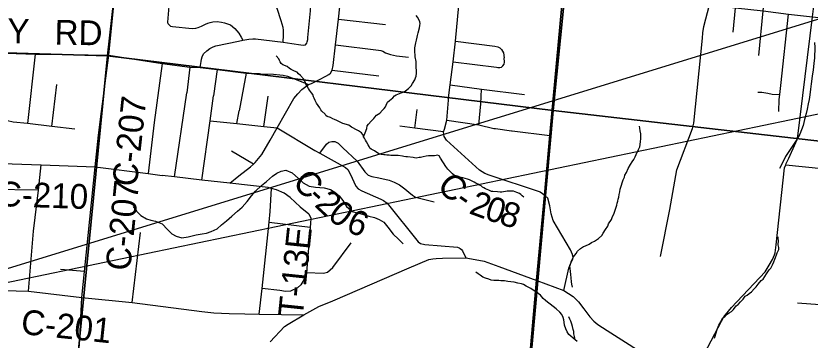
# Model space of a CAD drawing. Extents: x 0 to 34, y -2 to 22.
# Drawn here: x 5.919 to 7.738, y 16.052 to 16.795 of the extents above; entities that cross this region are included whole.
import ezdxf

# ---------------------------------------------------------------- set-up
doc = ezdxf.new("R2010")
doc.units = 0
for name, color, linetype in [('GM_X_City_Street', 7, 'Continuous'), ('GM_X_County_Road', 7, 'Continuous'), ('GM_X_County_Road_Text', 7, 'Continuous'), ('GM_X_Minor_River', 7, 'Continuous'), ('GM_X_Rail_Line', 7, 'Continuous'), ('GM_X_Section', 7, 'Continuous'), ('GM_X_Township_Road', 7, 'Continuous'), ('GM_X_Township_Road_Text', 7, 'Continuous'), ('SH_Data', 7, 'Continuous')]:
    doc.layers.add(name, color=color, linetype=linetype)

msp = doc.modelspace()

# ---------------------------------------------------------------- linework, layer by layer
at = {"layer": 'GM_X_City_Street'}
for p, q in [((6.6581, 16.7874), (6.7659, 16.7749)), ((6.6435, 16.6702), (6.7501, 16.6574)), ((6.984, 16.5934), (6.9858, 16.6272)), ((6.2824, 16.4258), (6.3103, 16.6188)), ((6.4872, 16.5414), (6.497, 16.6107)), ((6.4248, 16.548), (6.4308, 16.5773)), ((6.4631, 16.4553), (6.4127, 16.4848)), ((6.5018, 16.3463), (6.5046, 16.3991)), ((7.7088, 16.1375), (7.7832, 16.1312))]:
    msp.add_line(p, q, dxfattribs=at)
for points in [[(7.6208, 16.7039), (7.6305, 16.8061), (7.6519, 17.0096), (7.6625, 17.1149), (7.6673, 17.1631), (7.6723, 17.2097), (7.6784, 17.2661), (7.6863, 17.3438)], [(7.3952, 16.2431), (7.4169, 16.3509), (7.4324, 16.4422), (7.4685, 16.5369), (7.4715, 16.5488), (7.4913, 16.7438), (7.4923, 16.7556), (7.4943, 16.7707), (7.5074, 16.8201), (7.5148, 16.8521), (7.5294, 16.9123), (7.5314, 16.9213), (7.5357, 16.9362), (7.5392, 16.9489), (7.5442, 16.9615), (7.5505, 16.9743), (7.5547, 16.9827), (7.5547, 16.9956), (7.5546, 17.0201), (7.5573, 17.126)], [(6.5854, 16.7319), (6.5865, 16.7357), (6.5874, 16.7403), (6.5877, 16.7449), (6.5941, 16.8067), (6.5949, 16.8186), (6.5946, 16.8234), (6.5938, 16.8272), (6.5917, 16.8341), (6.5826, 16.851), (6.5807, 16.8593), (6.5804, 16.8706), (6.5892, 16.9384)], [(6.4094, 16.4112), (6.4299, 16.4281), (6.4567, 16.4492), (6.4631, 16.4553), (6.4669, 16.4591), (6.4823, 16.4772), (6.5016, 16.5099), (6.5176, 16.5383), (6.5556, 16.6057), (6.5651, 16.6164), (6.5739, 16.6258), (6.5891, 16.6379), (6.5959, 16.6397), (6.6145, 16.6491), (6.6292, 16.6569), (6.6356, 16.6607), (6.6394, 16.6638), (6.6435, 16.6702), (6.6458, 16.681), (6.6513, 16.7287), (6.6581, 16.7874), (6.6735, 16.9296)], [(6.5309, 16.7348), (6.5322, 16.7509), (6.532, 16.7619), (6.5314, 16.7683), (6.5269, 16.7835), (6.5176, 16.8118), (6.5134, 16.8189), (6.5074, 16.8272), (6.4893, 16.8506), (6.4799, 16.8633), (6.465, 16.8844), (6.4428, 16.9198)], [(7.5615, 16.7575), (7.5671, 16.8129), (7.5712, 16.8506), (7.5754, 16.9165)], [(6.2678, 16.7768), (6.267, 16.7801), (6.2702, 16.8171), (6.2713, 16.8208), (6.2724, 16.8225), (6.274, 16.8244), (6.2763, 16.8259), (6.2787, 16.8266), (6.3175, 16.8231), (6.3379, 16.8205), (6.3438, 16.8209), (6.3493, 16.822), (6.3608, 16.827), (6.3671, 16.8295), (6.3726, 16.8306), (6.3799, 16.831), (6.4356, 16.8227)], [(7.6664, 16.5759), (7.6671, 16.6032), (7.669, 16.6144), (7.6709, 16.6349), (7.6888, 16.7991)], [(6.2678, 16.7768), (6.27, 16.774), (6.2734, 16.7715), (6.2776, 16.7705), (6.3225, 16.7657), (6.3312, 16.7669), (6.3368, 16.7683), (6.3444, 16.7714), (6.3531, 16.7761), (6.3587, 16.7782), (6.3641, 16.7798), (6.3703, 16.7812), (6.3801, 16.7817), (6.3897, 16.7807), (6.3972, 16.7792), (6.4103, 16.7741), (6.4202, 16.7661), (6.4293, 16.7552), (6.4348, 16.7458), (6.4391, 16.7393)], [(6.3415, 16.6766), (6.3431, 16.6901), (6.3442, 16.6957), (6.346, 16.7011), (6.3487, 16.7076), (6.3561, 16.7149), (6.3636, 16.7204), (6.3712, 16.7242), (6.3771, 16.7264), (6.4286, 16.7365), (6.4391, 16.7393), (6.4523, 16.7412), (6.4619, 16.7424), (6.4675, 16.7424), (6.4866, 16.7399), (6.5309, 16.7348), (6.5513, 16.7318), (6.572, 16.7287), (6.5782, 16.7278), (6.5824, 16.7288), (6.5854, 16.7319)], [(6.9257, 16.7372), (7.016, 16.7256), (7.0227, 16.7238), (7.0275, 16.7215), (7.0312, 16.718), (7.0339, 16.714), (7.0356, 16.7098), (7.0372, 16.6984)], [(6.6513, 16.7287), (6.7494, 16.7165), (6.755, 16.7156), (6.7597, 16.714), (6.7658, 16.7101), (6.7767, 16.7061), (6.7911, 16.7029), (6.8185, 16.7001)], [(6.9205, 16.6895), (7.0201, 16.6771), (7.023, 16.6767), (7.0272, 16.6767), (7.0313, 16.6776), (7.0345, 16.6801), (7.037, 16.6841), (7.0378, 16.6885), (7.0372, 16.6984)], [(6.9137, 16.6365), (6.9858, 16.6272), (7.0838, 16.6148)], [(6.3452, 16.4186), (6.3637, 16.5544), (6.3715, 16.6115)], [(7.6182, 16.6199), (7.6272, 16.6202), (7.6412, 16.6174), (7.6509, 16.6152), (7.669, 16.6144)], [(6.3637, 16.5544), (6.4248, 16.548), (6.4872, 16.5414), (6.5176, 16.5383), (6.604, 16.4859)], [(7.6823, 16.4535), (7.7649, 16.4449), (7.8088, 16.4403), (7.8136, 16.4399), (7.8494, 16.4361), (7.854, 16.4356), (7.859, 16.4351)], [(6.5699, 16.3571), (6.5474, 16.3789), (6.5333, 16.3885), (6.5161, 16.3963), (6.5046, 16.3991), (6.4965, 16.4011), (6.4094, 16.4112), (6.3452, 16.4186), (6.2824, 16.4258), (6.2538, 16.4291)]]:
    msp.add_lwpolyline(points, dxfattribs=at)
at = {"layer": 'GM_X_County_Road'}
msp.add_line((6.4461, 16.6638), (6.4308, 16.5773), dxfattribs=at)
for points in [[(6.9101, 16.6067), (6.9137, 16.6365), (6.9205, 16.6895), (6.9257, 16.7372), (6.9402, 16.8926), (6.9541, 16.9885), (6.9627, 17.0648), (6.9675, 17.1013), (6.9705, 17.1364), (6.9735, 17.164), (6.9816, 17.2685), (6.9956, 17.3996)], [(6.1316, 16.7045), (6.1476, 16.867), (6.1481, 16.8719), (6.1555, 16.9383), (6.1634, 17.0422)], [(7.4637, 15.9561), (7.4964, 16.0209), (7.5352, 16.0954), (7.5404, 16.1047), (7.558, 16.1266), (7.6348, 16.2084), (7.6443, 16.2237), (7.6522, 16.2368), (7.6565, 16.247), (7.6579, 16.2514), (7.6603, 16.2699), (7.6794, 16.4469), (7.6823, 16.4535), (7.6835, 16.4563), (7.6891, 16.469), (7.7056, 16.5046), (7.7084, 16.5106), (7.7098, 16.5193), (7.7437, 16.7928), (7.7563, 16.8973), (7.7576, 16.9073)], [(7.4025, 16.8396), (7.4054, 16.8392), (7.4318, 16.8345), (7.4767, 16.8251), (7.5074, 16.8201), (7.5322, 16.8169), (7.5671, 16.8129), (7.6305, 16.8061), (7.6888, 16.7991), (7.6957, 16.7979), (7.7437, 16.7928), (7.806, 16.7861), (7.8851, 16.7752)], [(5.7642, 16.7123), (5.9195, 16.7087), (5.9635, 16.7073), (5.991, 16.7068), (6.1316, 16.7045)], [(6.0335, 15.759), (6.0434, 15.8458), (6.0484, 15.8945), (6.0497, 15.9221), (6.0535, 15.9613), (6.0646, 16.041), (6.0702, 16.1495), (6.0762, 16.2088), (6.1008, 16.4492), (6.1082, 16.5217), (6.1149, 16.5754), (6.1316, 16.7045)], [(6.1316, 16.7045), (6.254, 16.6855), (6.3172, 16.6773), (6.3415, 16.6766), (6.3799, 16.6719), (6.4461, 16.6638), (6.4767, 16.6624), (6.48, 16.6623)], [(6.48, 16.6623), (6.5088, 16.6611), (6.5236, 16.66), (6.531, 16.6591), (6.5408, 16.6566), (6.5573, 16.6505), (6.5891, 16.6379)], [(6.9004, 16.5355), (6.9063, 16.5557), (6.9095, 16.6017), (6.9101, 16.6067)], [(7.1196, 16.3908), (7.118, 16.3919), (7.0031, 16.4295), (6.9934, 16.4335), (6.9811, 16.4414), (6.9049, 16.5098), (6.8998, 16.5183), (6.8994, 16.5226), (6.8984, 16.5288), (6.9004, 16.5355)], [(6.604, 16.4859), (6.6148, 16.4799), (6.6741, 16.4472), (6.679, 16.4426), (6.6844, 16.4326), (6.698, 16.4045), (6.7031, 16.3987), (6.711, 16.3939), (6.7548, 16.3749), (6.7611, 16.3714), (6.7693, 16.3655), (6.8407, 16.2771), (6.846, 16.2735), (6.8557, 16.2706), (6.9302, 16.2645), (6.9343, 16.2632), (6.9369, 16.2617), (6.9399, 16.2591), (6.9417, 16.2562), (6.9492, 16.2405)], [(5.7771, 16.4603), (5.9772, 16.4534), (6.1008, 16.4492), (6.222, 16.4333), (6.2538, 16.4291)], [(7.1743, 16.1656), (7.1852, 16.2164), (7.1893, 16.2266), (7.1945, 16.2371), (7.195, 16.2412), (7.194, 16.2477), (7.1894, 16.2584), (7.1495, 16.3262), (7.1446, 16.3408), (7.1417, 16.3598), (7.1376, 16.377), (7.1302, 16.3835), (7.1196, 16.3908)], [(6.5014, 16.0479), (6.5342, 16.083), (6.5426, 16.0881), (6.5789, 16.1097), (6.613, 16.1287), (6.6448, 16.1416), (6.8198, 16.2173), (6.865, 16.2363), (6.8742, 16.2379), (6.8817, 16.2385), (6.8962, 16.2396), (6.9492, 16.2405), (6.971, 16.2361), (6.9918, 16.2325), (7.0255, 16.2203), (7.112, 16.1885)], [(5.7506, 16.1784), (5.8081, 16.1722), (5.8625, 16.1664), (5.9478, 16.1635), (6.0702, 16.1495), (6.1855, 16.1382), (6.345, 16.1172), (6.3726, 16.1142), (6.4077, 16.1125), (6.4437, 16.112), (6.4766, 16.1114), (6.5789, 16.1097)], [(7.112, 16.1885), (7.1743, 16.1656), (7.1952, 16.1517), (7.2074, 16.1396), (7.2198, 16.1237), (7.2337, 16.1048), (7.2425, 16.0951), (7.2522, 16.0876), (7.2734, 16.0738), (7.3847, 16.003), (7.4637, 15.9561)]]:
    msp.add_lwpolyline(points, dxfattribs=at)
at = {"layer": 'GM_X_Minor_River'}
for points in [[(6.7155, 16.5176), (6.7188, 16.5267), (6.7229, 16.5369), (6.7238, 16.5426), (6.727, 16.5463), (6.7325, 16.5537), (6.7391, 16.5593), (6.7411, 16.5623), (6.7446, 16.5675), (6.7524, 16.5722), (6.759, 16.5785), (6.7625, 16.5822), (6.7657, 16.5867), (6.7673, 16.5905), (6.7702, 16.5969), (6.7748, 16.6009), (6.7822, 16.6072), (6.7865, 16.6113), (6.79, 16.6135), (6.7939, 16.6153), (6.7973, 16.6167), (6.8015, 16.6181), (6.8073, 16.6206), (6.8104, 16.622), (6.8154, 16.6261), (6.8186, 16.6287), (6.8244, 16.6346), (6.8272, 16.6398), (6.8328, 16.6481), (6.8344, 16.653), (6.8357, 16.6567), (6.8362, 16.6632), (6.8364, 16.6697), (6.8358, 16.6762), (6.8356, 16.6823), (6.8357, 16.6857), (6.8355, 16.6906), (6.8338, 16.7006), (6.8332, 16.7059), (6.8326, 16.7117), (6.8329, 16.7216), (6.8351, 16.7329), (6.8368, 16.7394), (6.8381, 16.7458), (6.839, 16.7496), (6.8403, 16.7556), (6.8436, 16.7674), (6.8445, 16.773), (6.8447, 16.7776), (6.8444, 16.7814), (6.8419, 16.7868), (6.8389, 16.7915), (6.836, 16.7954)], [(7.748, 16.7339), (7.7489, 16.7225), (7.7484, 16.6989), (7.7466, 16.6853), (7.7448, 16.6713), (7.7429, 16.6565), (7.7406, 16.6391), (7.7388, 16.6266), (7.7374, 16.6141), (7.7357, 16.6035), (7.7335, 16.5936), (7.7314, 16.5808), (7.7293, 16.5709), (7.7255, 16.5573), (7.7218, 16.5437), (7.7145, 16.5234), (7.7063, 16.5095), (7.6996, 16.4998), (7.691, 16.4863), (7.6816, 16.4728), (7.6744, 16.4581), (7.6681, 16.4453)], [(6.5914, 16.6243), (6.5896, 16.6282), (6.5852, 16.6352), (6.5831, 16.6394), (6.5813, 16.6437), (6.5781, 16.6506), (6.5706, 16.658), (6.5666, 16.6616), (6.5629, 16.6655), (6.5568, 16.6679), (6.5493, 16.6716), (6.5456, 16.6744), (6.54, 16.6787), (6.5302, 16.6824), (6.5269, 16.6859), (6.5243, 16.6894), (6.5229, 16.6929), (6.5215, 16.6967), (6.5152, 16.703)], [(7.0826, 16.3794), (7.0788, 16.3826), (7.0755, 16.3854), (7.0721, 16.3874), (7.0661, 16.3902), (7.0624, 16.3918), (7.059, 16.3927), (7.0556, 16.3931), (7.0498, 16.3929), (7.0445, 16.3927), (7.0323, 16.3908), (7.0281, 16.3909), (7.0221, 16.3918), (7.0114, 16.3921), (7.0084, 16.3926), (7.0054, 16.3938), (7.0024, 16.395), (6.9982, 16.3967), (6.9949, 16.3986), (6.9911, 16.4007), (6.9881, 16.4026), (6.9844, 16.4054), (6.9806, 16.4067), (6.9769, 16.4091), (6.9724, 16.4111), (6.9683, 16.4139), (6.9653, 16.4155), (6.9611, 16.4175), (6.9581, 16.4187), (6.9536, 16.4204), (6.9423, 16.4233), (6.9389, 16.4242), (6.9351, 16.4255), (6.9279, 16.4264), (6.9242, 16.4284), (6.919, 16.4328), (6.916, 16.4355), (6.9082, 16.4433), (6.9035, 16.4499), (6.8918, 16.4686), (6.8885, 16.4744), (6.8848, 16.4752), (6.8813, 16.4749), (6.8775, 16.4743), (6.8676, 16.4742), (6.8642, 16.4739), (6.8585, 16.4733), (6.8516, 16.4716), (6.8458, 16.4702), (6.8428, 16.4699), (6.8359, 16.469), (6.8321, 16.4695), (6.8291, 16.4699), (6.8158, 16.4718), (6.812, 16.4719), (6.8079, 16.4728), (6.8048, 16.4736), (6.7942, 16.4747), (6.787, 16.4749), (6.7775, 16.4748), (6.7741, 16.4753), (6.7688, 16.4758), (6.7646, 16.4763), (6.7616, 16.4764), (6.7559, 16.4769), (6.7517, 16.4782), (6.7457, 16.4818), (6.7405, 16.4853), (6.7326, 16.489), (6.7297, 16.4914), (6.7282, 16.4956), (6.7261, 16.4995), (6.7217, 16.5061), (6.7199, 16.5099), (6.7177, 16.5145), (6.7155, 16.5176), (6.7152, 16.5207), (6.7105, 16.5265), (6.7037, 16.5317), (6.7004, 16.5329), (6.688, 16.5394), (6.6817, 16.5445), (6.6677, 16.5483), (6.6632, 16.5507), (6.6542, 16.5548), (6.6485, 16.5572), (6.6448, 16.5592), (6.6399, 16.562), (6.632, 16.5642), (6.6286, 16.5665), (6.6272, 16.5696), (6.6198, 16.5767), (6.6176, 16.5798), (6.615, 16.5844), (6.6077, 16.5945), (6.6045, 16.6007), (6.602, 16.6065), (6.6005, 16.6096), (6.5988, 16.6146), (6.5962, 16.6181), (6.5914, 16.6243)], [(7.1937, 16.173), (7.1924, 16.1799), (7.1914, 16.1849), (7.1909, 16.1944), (7.19, 16.2024), (7.189, 16.2093), (7.1884, 16.2158), (7.1878, 16.2215), (7.1899, 16.2283), (7.1915, 16.2332), (7.194, 16.2381), (7.1964, 16.2426), (7.2023, 16.2504), (7.2055, 16.2553), (7.2121, 16.262), (7.2187, 16.266), (7.2237, 16.2681), (7.2318, 16.2717), (7.2372, 16.2757), (7.2441, 16.2782), (7.2488, 16.2819), (7.2534, 16.2844), (7.2612, 16.2915), (7.2644, 16.2971), (7.2692, 16.3053), (7.2747, 16.3128), (7.2764, 16.3181), (7.2831, 16.3278), (7.2856, 16.3353), (7.2888, 16.3406), (7.2908, 16.347), (7.2938, 16.3561), (7.295, 16.3606), (7.2963, 16.3655), (7.2976, 16.37), (7.2988, 16.375), (7.2997, 16.3795), (7.301, 16.3856), (7.3023, 16.3912), (7.3032, 16.3973), (7.3062, 16.4067), (7.3078, 16.412), (7.3095, 16.4188), (7.3127, 16.4248), (7.314, 16.4294), (7.3172, 16.4361), (7.3216, 16.4452), (7.3265, 16.4545), (7.3304, 16.4601), (7.334, 16.4654), (7.3376, 16.4718), (7.34, 16.477), (7.3449, 16.4883), (7.3477, 16.4943), (7.349, 16.5004), (7.3496, 16.5072), (7.3505, 16.5129), (7.3507, 16.5194), (7.3504, 16.5243), (7.3491, 16.5312), (7.3481, 16.5373), (7.3471, 16.5419)], [(6.1879, 16.3577), (6.1953, 16.3473), (6.2049, 16.3376), (6.2184, 16.3293), (6.2282, 16.3264), (6.2391, 16.3243), (6.2538, 16.3183), (6.266, 16.3051), (6.2764, 16.2954), (6.2865, 16.2898), (6.299, 16.2861), (6.3134, 16.2881), (6.3321, 16.293), (6.3454, 16.2954), (6.3553, 16.2971), (6.366, 16.3007), (6.3798, 16.3065), (6.3903, 16.3157), (6.4011, 16.325), (6.4138, 16.3357), (6.427, 16.3476), (6.4374, 16.3565), (6.4491, 16.3696), (6.4585, 16.3823), (6.4678, 16.3927), (6.4814, 16.4057), (6.493, 16.4154), (6.5069, 16.4276), (6.5169, 16.4346), (6.5265, 16.439), (6.5375, 16.4414), (6.5518, 16.4354), (6.5663, 16.4221), (6.5771, 16.4124), (6.5906, 16.4045), (6.6049, 16.4023), (6.6254, 16.4004), (6.6393, 16.397), (6.6494, 16.3907), (6.6591, 16.3825), (6.6676, 16.3717), (6.6764, 16.3582), (6.6898, 16.3466), (6.6996, 16.3433), (6.7128, 16.34), (6.7271, 16.3359), (6.7407, 16.3329), (6.7508, 16.3281), (6.7616, 16.3218), (6.7712, 16.3102), (6.783, 16.2948), (6.7953, 16.2827), (6.8057, 16.2723)], [(7.5191, 16.0562), (7.5208, 16.0611), (7.5229, 16.0686), (7.5245, 16.0735), (7.5258, 16.0781), (7.5291, 16.086), (7.5334, 16.0935), (7.5375, 16.1017), (7.5425, 16.1054), (7.5468, 16.1106), (7.5526, 16.1146), (7.5577, 16.1172), (7.5623, 16.1216), (7.569, 16.1305), (7.5733, 16.1335), (7.5788, 16.1398), (7.5847, 16.1453), (7.5894, 16.1521), (7.5937, 16.1546), (7.5987, 16.1583), (7.6038, 16.1623), (7.6096, 16.1694), (7.6143, 16.1735), (7.6191, 16.1798), (7.6257, 16.188), (7.6304, 16.1917), (7.6344, 16.1977), (7.6383, 16.2033), (7.6443, 16.2126), (7.6478, 16.2167), (7.6522, 16.2246), (7.6551, 16.2314), (7.6571, 16.237), (7.6591, 16.2412), (7.6608, 16.2468), (7.6628, 16.2521), (7.6661, 16.2596), (7.6662, 16.2638), (7.6652, 16.2699), (7.6655, 16.2798), (7.6652, 16.2844), (7.6646, 16.2886)], [(7.1999, 16.0521), (7.1855, 16.0647), (7.1818, 16.0709), (7.1782, 16.0774), (7.1758, 16.0863), (7.1744, 16.0932), (7.1738, 16.0985), (7.1721, 16.1035), (7.1692, 16.1104), (7.1652, 16.1159), (7.1566, 16.1237), (7.1499, 16.1285), (7.1425, 16.134), (7.1369, 16.1384), (7.132, 16.1423), (7.1269, 16.1474), (7.1202, 16.1548), (7.1154, 16.1588), (7.1109, 16.162), (7.1064, 16.1647), (7.0986, 16.1703), (7.0881, 16.1755), (7.0817, 16.1788), (7.0772, 16.1804), (7.0689, 16.1825), (7.0602, 16.1843), (7.0526, 16.1853), (7.0458, 16.1862), (7.0378, 16.1872), (7.0298, 16.1878), (7.0253, 16.1883), (7.0139, 16.1887), (7.0078, 16.1892), (7.0022, 16.1913), (6.9946, 16.1938), (6.9886, 16.1962), (6.9823, 16.2002), (6.9778, 16.2037), (6.9726, 16.2073)], [(7.2044, 16.0485), (7.1999, 16.0521), (7.1983, 16.0601), (7.1969, 16.0663), (7.1967, 16.0712), (7.1957, 16.0762), (7.1939, 16.0827), (7.1926, 16.0885), (7.1897, 16.095), (7.1876, 16.1), (7.1854, 16.1047)]]:
    msp.add_lwpolyline(points, dxfattribs=at)
at = {"layer": 'GM_X_Rail_Line'}
for points in [[(7.3254, 18.3889), (7.2924, 18.0527), (7.2805, 17.9249), (7.2705, 17.818), (7.2479, 17.5755), (7.2301, 17.3765), (7.2142, 17.2276), (7.2013, 17.0768), (7.1819, 16.9294), (7.1729, 16.8603), (7.1419, 16.5212), (7.1299, 16.384), (7.1117, 16.189), (7.0415, 15.3869), (7.041, 15.3813), (7.0162, 15.1361), (7.0052, 15.0295), (7.018, 15.0319), (7.3068, 15.0956), (7.4995, 15.1593), (7.5948, 15.214), (7.6912, 15.289), (7.9856, 15.5639)], [(7.0415, 15.3869), (7.1117, 16.189), (7.1299, 16.384), (7.1419, 16.5212), (7.1729, 16.8603)]]:
    msp.add_lwpolyline(points, dxfattribs=at)
at = {"layer": 'GM_X_Section'}
for points in [[(5.25, 17.7471), (6.241, 17.6971), (6.1288, 16.703), (5.1427, 16.732)], [(6.241, 17.6971), (7.2505, 17.5778), (7.1499, 16.5781), (6.1288, 16.703)], [(7.2505, 17.5778), (8.2288, 17.4754), (8.1243, 16.4653), (7.1499, 16.5781)], [(6.1288, 16.703), (6.0281, 15.6802), (5.0363, 15.7105), (5.1427, 16.732)], [(7.1499, 16.5781), (7.0595, 15.5763), (6.0281, 15.6802), (6.1288, 16.703)], [(8.1243, 16.4653), (8.036, 15.6699), (8.0185, 15.6495), (8.0091, 15.6379), (8.0044, 15.6324), (7.9936, 15.622), (7.9816, 15.6105), (7.958, 15.591), (7.9342, 15.576), (7.9154, 15.5647), (7.9046, 15.5577), (7.8981, 15.5526), (7.864, 15.5196), (7.8404, 15.4978), (7.8376, 15.4949), (7.0595, 15.5763), (7.1499, 16.5781)]]:
    msp.add_lwpolyline(points, close=True, dxfattribs=at)
at = {"layer": 'GM_X_Township_Road'}
for p, q in [((5.9635, 16.7073), (5.9459, 16.5482)), ((6.3172, 16.6773), (6.3103, 16.6188)), ((6.3799, 16.6719), (6.3715, 16.6115)), ((6.0012, 16.5411), (6.013, 16.6378)), ((6.9793, 16.5454), (6.984, 16.5934)), ((6.8326, 16.5376), (6.8382, 16.5801)), ((7.0553, 16.5315), (7.1421, 16.5206)), ((6.4992, 16.3217), (6.5931, 16.3102)), ((6.1855, 16.1382), (6.2043, 16.2983)), ((6.0762, 16.2088), (6.0215, 16.2133))]:
    msp.add_line(p, q, dxfattribs=at)
for points in [[(6.254, 16.6855), (6.2354, 16.5506), (6.222, 16.4333)], [(6.0541, 16.535), (6.0012, 16.5411), (5.9459, 16.5482), (5.9128, 16.551), (5.8995, 16.5546), (5.894, 16.5601), (5.8901, 16.5645), (5.8872, 16.5693), (5.8844, 16.5768), (5.8833, 16.5859), (5.8846, 16.6524)], [(6.9063, 16.5557), (6.9793, 16.5454), (7.0135, 16.537), (7.0173, 16.5365)], [(6.8984, 16.5288), (6.8326, 16.5376), (6.7981, 16.5423)], [(7.0173, 16.5365), (7.0543, 16.5316), (7.0553, 16.5315)], [(6.6148, 16.4799), (6.6301, 16.5009), (6.6356, 16.5056), (6.6426, 16.507), (6.6493, 16.5066), (6.6575, 16.5028), (6.6679, 16.4926), (6.701, 16.4615), (6.7183, 16.4376), (6.7256, 16.43), (6.7342, 16.4266), (6.7504, 16.4233), (6.7742, 16.4179), (6.7857, 16.414), (6.7979, 16.4079), (6.8096, 16.3987), (6.8191, 16.3907), (6.8271, 16.3836), (6.8344, 16.3794), (6.877, 16.3684)], [(5.9478, 16.1635), (5.9595, 16.3011), (5.9705, 16.3953), (5.9772, 16.4534)], [(5.9705, 16.3953), (5.861, 16.3972), (5.824, 16.3976)], [(6.5699, 16.3571), (6.5903, 16.3408), (6.5944, 16.331), (6.5935, 16.3189), (6.5931, 16.3102)], [(6.4766, 16.1114), (6.4829, 16.17), (6.4992, 16.3217), (6.5018, 16.3463)], [(6.5931, 16.3102), (6.5846, 16.2064), (6.5805, 16.1946), (6.5759, 16.1859), (6.5715, 16.1784), (6.5637, 16.1713), (6.548, 16.1637), (6.5364, 16.1629), (6.5234, 16.1651), (6.4829, 16.17)], [(6.5846, 16.2064), (6.6238, 16.2048), (6.6324, 16.2072), (6.645, 16.2179), (6.6871, 16.2746)]]:
    msp.add_lwpolyline(points, dxfattribs=at)
at = {"layer": 'SH_Data'}
msp.add_lwpolyline([(5.5739, 16.1159), (9.9248, 17.4558), (9.9244, 17.0214)], close=True, dxfattribs=at)

# ---------------------------------------------------------------- texts
at = {"layer": 'GM_X_County_Road_Text'}
for s, height, rotation, p in [('FOLEY', 0.05682, 358.5154, (5.7004, 16.7374)), ('RD', 0.05682, 359.0128, (6.0073, 16.729)), ('C-207', 0.05682, 83.8103, (6.1959, 16.4019)), ('C', 0.0568, 316.4366, (6.5497, 16.4085)), ('C', 0.0568, 317.736, (6.8808, 16.4)), ('C-210', 0.05682, 358.0725, (5.8769, 16.3589)), ('C-207', 0.05682, 84.2359, (6.1807, 16.2089)), ('-', 0.0568, 316.5426, (6.5836, 16.3763)), ('2', 0.0568, 316.9809, (6.6008, 16.3599)), ('2', 0.0568, 339.5626, (6.9544, 16.3429)), ('0', 0.0568, 321.933, (6.6305, 16.3325)), ('-', 0.0568, 324.7042, (6.9212, 16.3638)), ('0', 0.0568, 341.9873, (6.9897, 16.3298)), ('8', 0.0568, 342.1298, (7.0231, 16.3189)), ('6', 0.0568, 337.3396, (6.6724, 16.3025)), ('C-201', 0.05682, 353.984, (5.929, 16.0661))]:
    msp.add_text(s, height=height, rotation=rotation, dxfattribs=at).set_placement(p)
at = {"layer": 'GM_X_Township_Road_Text'}
msp.add_text('T-13E', height=0.05682, rotation=84.0753, dxfattribs=at).set_placement((6.5758, 16.1023))

doc.saveas('drawing.dxf')
